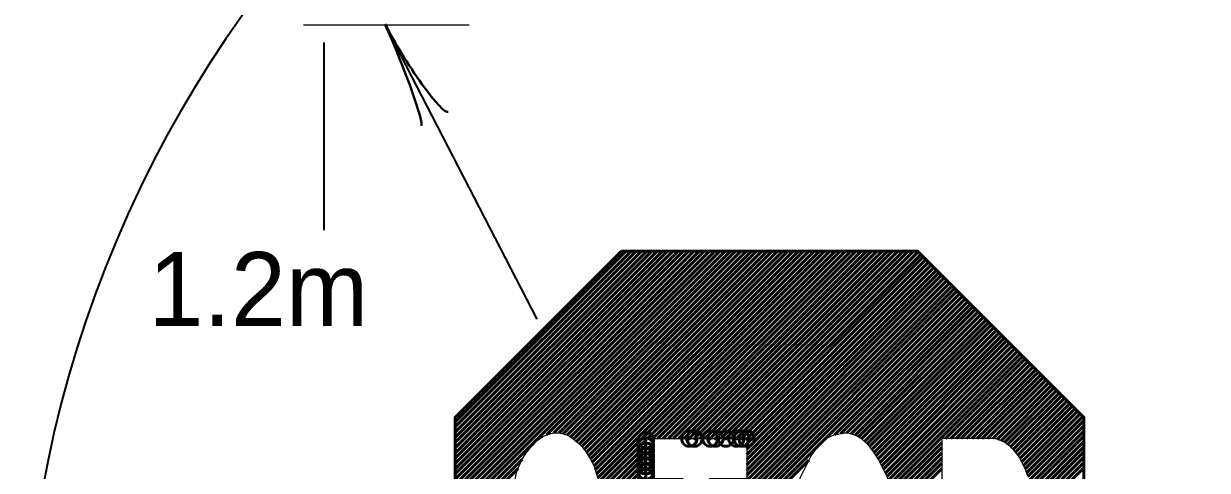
# Model space of a CAD drawing. Extents: x 1081 to 1936, y -630 to -24.
# Drawn here: x 1734.04 to 1772.44, y -269.26 to -254.76 of the extents above; entities that cross this region are included whole.
import ezdxf
from ezdxf.enums import TextEntityAlignment as Align

# ---------------------------------------------------------------- set-up
doc = ezdxf.new("R2010")
doc.units = 0
doc.header["$PDMODE"] = 32
doc.header["$PDSIZE"] = 0.5
doc.layers.add('1', color=7, linetype='Continuous', lineweight=53)
doc.layers.add('4', color=7, linetype='Continuous', lineweight=25)

msp = doc.modelspace()

# ---------------------------------------------------------------- linework, layer by layer
at = {"layer": '1', "lineweight": 35}
for p, q in [((1750.7, -264.357), (1745.767, -254.796)), ((1743.79, -261.462), (1743.79, -255.379))]:
    msp.add_line(p, q, dxfattribs=at)
at = {"layer": '1'}
for p, q in [((1748.036, -267.682), (1753.574, -262.144)), ((1748.036, -267.852), (1753.743, -262.144)), ((1748.036, -268.021), (1753.913, -262.144)), ((1748.036, -268.191), (1754.083, -262.144)), ((1748.036, -268.361), (1754.252, -262.144)), ((1748.036, -268.531), (1754.422, -262.144)), ((1748.036, -268.7), (1754.592, -262.144)), ((1748.036, -268.87), (1754.762, -262.144)), ((1748.036, -269.04), (1754.931, -262.144)), ((1748.036, -269.209), (1755.101, -262.144)), ((1748.036, -269.379), (1755.271, -262.144)), ((1748.036, -269.549), (1755.44, -262.144)), ((1748.036, -269.719), (1755.61, -262.144)), ((1748.036, -269.888), (1755.78, -262.144)), ((1748.036, -270.058), (1755.949, -262.144)), ((1748.036, -270.228), (1756.119, -262.144)), ((1748.036, -270.397), (1756.289, -262.144)), ((1748.036, -270.567), (1756.459, -262.144)), ((1748.036, -270.737), (1756.628, -262.144)), ((1748.036, -270.906), (1756.798, -262.144)), ((1751.003, -268.109), (1756.968, -262.144)), ((1751.239, -268.043), (1757.137, -262.144)), ((1751.409, -268.043), (1757.307, -262.144)), ((1751.546, -268.075), (1757.477, -262.144)), ((1751.678, -268.113), (1757.647, -262.144)), ((1751.78, -268.181), (1757.816, -262.144)), ((1751.879, -268.251), (1757.986, -262.144)), ((1751.974, -268.326), (1758.156, -262.144)), ((1752.062, -268.408), (1758.325, -262.144)), ((1752.147, -268.492), (1758.495, -262.144)), ((1752.227, -268.582), (1758.665, -262.144)), ((1752.298, -268.68), (1758.834, -262.144)), ((1752.364, -268.785), (1759.004, -262.144)), ((1752.429, -268.889), (1759.174, -262.144)), ((1752.488, -269), (1759.344, -262.144)), ((1752.543, -269.115), (1759.513, -262.144)), ((1752.582, -269.246), (1759.683, -262.144)), ((1752.621, -269.376), (1759.853, -262.144)), ((1752.662, -269.504), (1760.022, -262.144)), ((1752.701, -269.635), (1760.192, -262.144)), ((1754.277, -268.23), (1760.362, -262.144)), ((1754.446, -268.23), (1760.532, -262.144)), ((1754.616, -268.23), (1760.701, -262.144)), ((1754.786, -268.23), (1760.871, -262.144)), ((1754.955, -268.23), (1761.041, -262.144)), ((1755.125, -268.23), (1761.21, -262.144)), ((1755.295, -268.23), (1761.38, -262.144)), ((1755.464, -268.23), (1761.55, -262.144)), ((1755.634, -268.23), (1761.719, -262.144)), ((1755.804, -268.23), (1761.889, -262.144)), ((1755.974, -268.23), (1762.059, -262.144)), ((1756.143, -268.23), (1762.229, -262.144)), ((1756.313, -268.23), (1762.398, -262.144)), ((1756.483, -268.23), (1762.568, -262.144)), ((1756.652, -268.23), (1762.738, -262.144)), ((1756.822, -268.23), (1762.907, -262.144)), ((1756.992, -268.23), (1763.056, -262.165)), ((1757.162, -268.23), (1763.141, -262.25)), ((1757.331, -268.23), (1763.226, -262.335)), ((1757.497, -268.234), (1763.311, -262.42)), ((1757.497, -268.404), (1763.396, -262.504)), ((1757.497, -268.573), (1763.481, -262.589)), ((1757.497, -268.743), (1763.566, -262.674)), ((1757.497, -268.913), (1763.65, -262.759)), ((1757.497, -269.082), (1763.735, -262.844)), ((1757.497, -269.252), (1763.82, -262.929)), ((1757.497, -269.422), (1763.905, -263.014)), ((1756.281, -270.808), (1763.99, -263.098)), ((1756.281, -270.977), (1764.075, -263.183)), ((1756.281, -271.147), (1764.159, -263.268)), ((1756.281, -271.317), (1764.244, -263.353)), ((1756.281, -271.486), (1764.329, -263.438)), ((1756.281, -271.656), (1764.414, -263.523)), ((1756.281, -271.826), (1764.499, -263.607)), ((1756.281, -271.995), (1764.584, -263.692)), ((1760.343, -268.103), (1764.669, -263.777)), ((1760.555, -268.061), (1764.754, -263.862)), ((1760.743, -268.043), (1764.838, -263.947)), ((1760.881, -268.074), (1764.923, -264.032)), ((1761.01, -268.115), (1765.008, -264.117)), ((1761.122, -268.173), (1765.093, -264.201)), ((1761.222, -268.242), (1765.178, -264.286)), ((1761.313, -268.321), (1765.263, -264.371)), ((1761.405, -268.399), (1765.347, -264.456)), ((1761.482, -268.492), (1765.432, -264.541)), ((1761.554, -268.589), (1765.517, -264.626)), ((1761.626, -268.687), (1765.602, -264.711)), ((1761.691, -268.791), (1765.687, -264.795)), ((1761.756, -268.896), (1765.772, -264.88)), ((1761.814, -269.007), (1765.857, -264.965)), ((1761.871, -269.12), (1765.941, -265.05)), ((1761.927, -269.234), (1766.026, -265.135)), ((1761.984, -269.347), (1766.111, -265.22)), ((1762.041, -269.46), (1766.196, -265.305)), ((1762.085, -269.585), (1766.281, -265.389)), ((1762.124, -269.716), (1766.366, -265.474)), ((1762.158, -269.851), (1766.451, -265.559)), ((1763.95, -268.23), (1766.535, -265.644)), ((1764.119, -268.23), (1766.62, -265.729)), ((1764.289, -268.23), (1766.705, -265.814)), ((1764.459, -268.23), (1766.79, -265.898)), ((1764.629, -268.23), (1766.875, -265.983)), ((1764.798, -268.23), (1766.96, -266.068)), ((1764.968, -268.23), (1767.045, -266.153)), ((1765.138, -268.23), (1767.129, -266.238)), ((1765.307, -268.23), (1767.214, -266.323)), ((1765.477, -268.23), (1767.299, -266.408)), ((1765.62, -268.256), (1767.384, -266.492)), ((1765.747, -268.299), (1767.469, -266.577)), ((1765.868, -268.348), (1767.554, -266.662)), ((1765.96, -268.425), (1767.639, -266.747)), ((1766.058, -268.497), (1767.723, -266.832)), ((1766.143, -268.582), (1767.808, -266.917)), ((1766.219, -268.676), (1767.893, -267.002)), ((1766.292, -268.773), (1767.978, -267.086)), ((1766.362, -268.872), (1768.063, -267.171)), ((1766.418, -268.985), (1768.148, -267.256)), ((1766.475, -269.099), (1768.232, -267.341)), ((1766.531, -269.212), (1768.317, -267.426)), ((1766.576, -269.337), (1768.402, -267.511)), ((1766.618, -269.464), (1768.436, -267.647)), ((1766.661, -269.592), (1768.436, -267.816)), ((1766.695, -269.727), (1768.436, -267.986)), ((1752.73, -269.776), (1754.223, -268.284)), ((1762.197, -269.983), (1763.826, -268.353)), ((1766.728, -269.863), (1768.436, -268.156)), ((1766.753, -270.009), (1768.436, -268.326)), ((1752.758, -269.918), (1754.223, -268.453)), ((1752.773, -270.072), (1754.223, -268.623)), ((1752.789, -270.227), (1754.223, -268.793)), ((1762.238, -270.111), (1763.826, -268.523)), ((1762.267, -270.252), (1763.826, -268.692)), ((1766.777, -270.154), (1768.436, -268.495)), ((1766.791, -270.31), (1768.436, -268.665)), ((1748.036, -271.076), (1750.208, -268.904)), ((1752.804, -270.381), (1754.223, -268.962)), ((1752.819, -270.535), (1754.223, -269.132)), ((1756.281, -272.165), (1759.517, -268.929)), ((1762.295, -270.394), (1763.826, -268.862)), ((1762.32, -270.538), (1763.826, -269.032)), ((1766.806, -270.464), (1768.436, -268.835)), ((1766.82, -270.62), (1768.436, -269.004)), ((1766.82, -270.79), (1768.436, -269.174)), ((1748.036, -271.246), (1750.082, -269.2)), ((1762.344, -270.684), (1763.826, -269.201))]:
    msp.add_line(p, q, dxfattribs=at)
msp.add_lwpolyline([(1753.436, -262.144), (1763.036, -262.144), (1768.436, -267.544), (1768.436, -277.144), (1763.036, -282.544), (1753.436, -282.544), (1748.036, -277.144), (1748.036, -267.544)], close=True, dxfattribs=at)
at = {"layer": '1', "lineweight": 25}
for points in [[(1750.325, -268.728), (1750.418, -268.604), (1750.512, -268.479), (1750.575, -268.417), (1750.699, -268.292), (1750.886, -268.167), (1751.011, -268.105), (1751.229, -268.043), (1751.292, -268.043), (1751.416, -268.043), (1751.666, -268.105), (1751.759, -268.167), (1751.853, -268.23), (1752.009, -268.354), (1752.134, -268.479), (1752.196, -268.541), (1752.289, -268.666)], [(1758.837, -272.221), (1758.837, -272.034), (1758.837, -271.722), (1758.869, -271.285), (1758.9, -270.911), (1758.962, -270.599), (1759.024, -270.225), (1759.118, -269.913), (1759.18, -269.664), (1759.243, -269.477), (1759.336, -269.29), (1759.555, -268.853), (1759.586, -268.791), (1759.679, -268.666), (1759.773, -268.541), (1759.866, -268.417), (1759.929, -268.354), (1760.085, -268.23), (1760.209, -268.167), (1760.334, -268.105), (1760.646, -268.043), (1760.615, -268.043)], [(1760.615, -268.043), (1760.771, -268.043), (1760.989, -268.105), (1761.114, -268.167), (1761.207, -268.23), (1761.425, -268.417), (1761.613, -268.666), (1761.768, -268.916), (1761.956, -269.29), (1762.049, -269.477), (1762.111, -269.664), (1762.174, -269.913), (1762.236, -270.1), (1762.299, -270.412), (1762.361, -270.786), (1762.392, -271.036), (1762.423, -271.285), (1762.455, -271.66), (1762.455, -271.847), (1762.455, -272.221)], [(1765.541, -268.23), (1763.826, -268.23), (1763.826, -276.15), (1764.668, -276.15), (1764.668, -273.343), (1765.541, -273.343)], [(1766.601, -269.415), (1766.539, -269.227), (1766.477, -269.103), (1766.415, -268.978), (1766.352, -268.853), (1766.259, -268.728), (1766.165, -268.604), (1766.103, -268.541), (1766.04, -268.479), (1765.947, -268.417), (1765.884, -268.354), (1765.728, -268.292), (1765.541, -268.23)], [(1752.071, -274.092), (1752.071, -273.905), (1752.071, -273.593), (1751.978, -273.281), (1751.822, -273.094), (1751.666, -272.969), (1750.668, -272.47), (1750.481, -272.345), (1750.263, -272.096), (1750.138, -271.847), (1750.013, -271.597), (1749.92, -271.161), (1749.888, -270.786), (1749.888, -270.225), (1749.951, -269.726), (1750.044, -269.29), (1750.2, -268.916), (1750.325, -268.728)], [(1752.289, -268.666), (1752.445, -268.916), (1752.539, -269.103), (1752.632, -269.415), (1752.695, -269.601), (1752.757, -269.913), (1752.788, -270.225), (1752.82, -270.537), (1752.071, -270.599)]]:
    msp.add_lwpolyline(points, dxfattribs=at)
msp.add_lwpolyline([(1754.223, -268.23), (1757.497, -268.23), (1757.497, -269.539), (1756.281, -269.539), (1756.281, -276.15), (1755.439, -276.15), (1755.439, -269.539), (1754.223, -269.539)], close=True, dxfattribs=at)
msp.add_lwpolyline([(1754.223, -268.23), (1757.497, -268.23), (1757.497, -269.539), (1756.281, -269.539), (1756.281, -276.15), (1755.439, -276.15), (1755.439, -269.539), (1754.223, -269.539)], close=True, dxfattribs=at)
at = {"layer": '1', "lineweight": 35}
msp.add_arc((1772.44, -276.723), 38.4, 90, 180, dxfattribs=at)
at = {"layer": '1', "lineweight": 40}
for centre, major_axis, ratio, start_param, end_param in [((1746.158, -256.107), (0.779, -1.97), 0.07063, 6.282307, 8.559703), ((1746.662, -255.807), (-1.149, 1.818), 0.122415, 0.896353, 3.141593)]:
    msp.add_ellipse(centre, major_axis=major_axis, ratio=ratio, start_param=start_param, end_param=end_param, dxfattribs=at)
at = {"layer": '1'}
for p in [(1755.634, -268.23), (1755.804, -268.23), (1756.313, -268.23), (1756.483, -268.23), (1756.822, -268.23), (1757.162, -268.23), (1757.331, -268.23), (1757.497, -268.234), (1754.223, -268.284), (1754.223, -268.453), (1754.223, -268.623), (1754.223, -268.793), (1754.223, -268.962), (1754.223, -269.132), (1754.223, -269.302), (1754.223, -269.471)]:
    msp.add_point(p, dxfattribs=at)
at = {"layer": '4'}
msp.add_line((1743.121, -254.796), (1748.497, -254.796), dxfattribs=at)

# ---------------------------------------------------------------- texts
at = {"layer": '1'}
msp.add_text('1.2m', height=2.4, dxfattribs=at).set_placement((1741.653, -264.576), align=Align.CENTER)

doc.saveas('drawing.dxf')
